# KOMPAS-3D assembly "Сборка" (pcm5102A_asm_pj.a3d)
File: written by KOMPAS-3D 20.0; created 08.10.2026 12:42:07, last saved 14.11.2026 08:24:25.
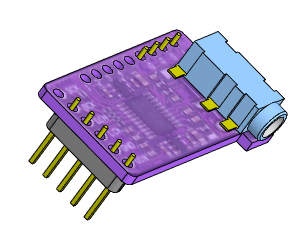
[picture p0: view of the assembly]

Document properties: Полное имя файла: D:\myProjects\Progect_esp32\box_compas\цап ацп\pcm5102A_asm_pj.a3d

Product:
- Part/product: Сборка
    Масса: 0.00967177
  - Component [detail]: Деталь  | Масса: 0.000635679; source file: ..\разъемы\pls_5.m3d
  - Component [detail]: Деталь  | Масса: 0.00239431; source file: ..\разъемы\PJ-327A.m3d
  - Component [detail]: Деталь  | Масса: 0.00613645; source file: pcm5102A.m3d
  - Component [detail]: Деталь  | Масса: 0.000505328; source file: ..\разъемы\pls_4.m3d

Referenced files in D:\myProjects\Progect_esp32\box_compas\цап ацп\: pcm5102A.m3d
Referenced files in D:\myProjects\Progect_esp32\box_compas\разъемы\: pls_4.m3d, PJ-327A.m3d, pls_5.m3d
